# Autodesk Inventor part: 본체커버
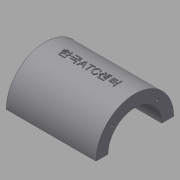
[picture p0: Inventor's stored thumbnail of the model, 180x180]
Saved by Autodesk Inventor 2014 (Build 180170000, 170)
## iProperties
Created: 2015-12
Part Number: 본체커버
Material: 일반
Document SubType Name: Modeling
Designer: mduedu
Density: 1 g/cm^3
Mass: 64.5736 g
Surface Area: 167.085 cm^2
Volume: 64.5736 cm^3
Appearance: 기본값
Author: mduedu
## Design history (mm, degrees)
sketch "스케치1"
  geometry: L1 (45, 40)-(-45, 40); L2 (-45, 40)-(-45, -40); L3 (-45, -40)-(45, -40); L4 (45, -40)-(45, 40); L5 (45, 40)-(-45, -40); L6 (-45, 40)-(45, -40); 1 further point
  constraints: 12 end point, 2 midpoint, 2 parallel, 1 horizontal, 1 perpendicular
  dimensions: "d0" = 90 distance of L2.end L3.end; "d2" = 80 distance of L1.end L2.end
extrude "돌출1" new body sketch "스케치1" distance "d3" = 10; taper "d4" = 0 deg
sketch "스케치2"
  geometry: L1 (0, 40)-(0, -40) reference; C1 r 32.5 at (80, 0); 1 further point
  constraints: 1 centre point
  dimensions: "d5" = 65 diameter of C1; "d6" = 80 distance from line of C1.centre L1
extrude "돌출2" join sketch "스케치2" stored distance "d7" = 75; taper "d8" = 0 deg
sketch "스케치3"
  geometry: L1 (-27.5, -20)-(27.5, -20); L2 (27.5, -20)-(27.5, 20); L3 (27.5, 20)-(-27.5, 20); L4 (-27.5, 20)-(-27.5, -20); L5 (-27.5, -20)-(27.5, 20); L6 (27.5, -20)-(-27.5, 20); 1 further point
  constraints: 12 end point, 2 midpoint, 2 parallel, 1 horizontal, 1 perpendicular
  dimensions: "d9" = 55 distance of L2.end L3.end; "d11" = 40 distance of L1.end L2.end
extrude "돌출3" new body sketch "스케치3" stored distance "d12" = 75; taper "d13" = 0 deg
fillet "모깎기1"
fillet "모깎기2"
feature "결합1"
  node "솔리드2"
fillet "모깎기3" dims "d14" = 10
sketch "스케치4"
  geometry: L1 (-37.5, 47.5)-(37.5, 47.5) reference; L2 (35, 10)-(45, 10) reference; L3 (32.5, 47.5)-(40, 10); L4 (37.5, 47.5)-(37.5, 112.5) reference; L5 (45, 10)-(45, 0) reference; 1 further point
  constraints: 2 end point, 1 midpoint, 1 point on line
  dimensions: "d15" = 5 distance from line of L3.start L4; "d16" = 5 distance from line of L3.end L5
sketch "스케치5"
  geometry: L1 (10, 40)-(10, 30) reference; L2 (10, 35)-(56.569, 22.522); L3 (0, 40)-(10, 40) reference; 2 further points
  constraints: 2 end point, 1 midpoint, 2 other
  dimensions: "d17" = 5 distance from line of L2.start L3; "d18" = 15 deg angle of L2 L3
feature "리브1" dims "d19" = 1, "d20" = 6, "d21" = 0, "d22" = 0, "d23" = 1, "d24" = 1
feature "리브2" dims "d25" = 1, "d26" = 6, "d27" = 0, "d28" = 0, "d29" = 1, "d30" = 1
fillet "모깎기4" dims "d31" = 2
fillet "모깎기5" dims "d32" = 2
fillet "모깎기6" dims "d33" = 2
sketch "스케치6"
  geometry: A1 r 10 centre (-35, 30) between (-35, 40) and (-45, 30) reference; A2 r 10 centre (35, 30) between (45, 30) and (35, 40) reference; A3 r 10 centre (35, -30) between (35, -40) and (45, -30) reference; A4 r 10 centre (-35, -30) between (-45, -30) and (-35, -40) reference; 5 further points
  constraints: 4 coincident
hole "구멍1" sketch "스케치6" at (-35, 30), (35, 30), (35, -30), (-35, -30) diameter "d34" = 7; stored, may be unused: countersink angle "d38" = 90 deg, drill point angle "d40" = 118 deg; dims "d35" = 6, "d36" = 12, "d37" = 3, "d39" = 8
fillet "모깎기7" dims "d41" = 2
hole "구멍2" diameter "d44" = 45; stored, may be unused: countersink angle "d48" = 90 deg, drill point angle "d50" = 118 deg; dims "d42" = 10, "d43" = 10, "d45" = 6, "d46" = 4, "d47" = 2, "d49" = 8
sketch "스케치7" dims "d52" = 26.5
  geometry: L1 (0, 0)-(32.5, 0); L2 (0, 0)-(22.981, 22.981); A1 r 32.5 centre (0, 0) between (32.5, 0) and (22.981, 22.981) reference; 3 further points
  constraints: 4 end point, 2 point on circle, 1 coincident, 1 horizontal, 1 point on line, 3 other
  dimensions: "d51" = 45 deg angle of L2 L1
hole "구멍3" sketch "스케치7" at (18.738, 18.738) diameter "d54" = 2.459; stored, may be unused: countersink angle "d58" = 90 deg, drill point angle "d60" = 118 deg; dims "d55" = 8, "d56" = 4, "d57" = 2, "d59" = 10
sketch "스케치13"
  geometry: L1 (-45, 80)-(105, 80); L2 (105, 80)-(105, -30); L3 (105, -30)-(-45, -30); L4 (-45, -30)-(-45, 80); L5 (0, 0)-(60, 0) reference; C1 r 32.5 at (30, 80) reference; 1 further point
  constraints: 8 end point, 2 parallel, 1 coincident, 1 horizontal, 1 midpoint, 1 perpendicular
  dimensions: "d99" = 30 distance between parallel lines of L3 L5; "d126" = 150 distance between parallel lines of L2 L4
extrude "돌출8" cut sketch "스케치13" stored distance "d97" = 10; taper "d98" = 0 deg
node "작업 평면2"
sketch "스케치14"
  geometry: 2 further points
  constraints: 1 coincident, 1 other
feature "엠보싱1" sketch "스케치14" dims "d102" = 0.5, "d103" = 0
sketch "스케치18"
  geometry: L1 (0, -10)-(0, 0) reference; L2 (75, 0)-(75, -10) reference; L3 (0, -5)-(75, -5); C1 r 1.5 at (13, -5); 1 further point
  constraints: 2 end point, 2 midpoint, 1 centre point, 1 point on line
  dimensions: "d127" = 3 diameter of C1; "d128" = 13 distance from line of L1 C1.centre
extrude "돌출9" cut sketch "스케치18" distance "d129" = 2; taper "d130" = 0 deg
chamfer "모따기2" distance "d131" = 0.5; stored, may be unused: second distance "d132" = 2, angle "d133" = 45 deg
fillet "모깎기12" dims "d134" = 0.1
node "솔리드1"
mirror "대칭1"
mirror "대칭2"
pattern_circular "원형 패턴1" dims angle "d62" = 360 deg
mirror "대칭3"
mirror "대칭5"
mirror "대칭6"
